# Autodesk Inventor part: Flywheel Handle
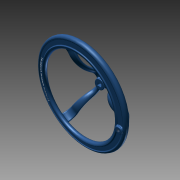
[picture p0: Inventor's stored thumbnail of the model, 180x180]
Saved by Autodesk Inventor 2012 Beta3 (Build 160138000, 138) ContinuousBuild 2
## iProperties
Created: 2010-12
Part Number: Flywheel Handle
Document SubType Name: Modeling
Designer: Thom Tremblay
Density: 1 g/cm^3
Material: Default
Author: Thom Tremblay
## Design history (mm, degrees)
sketch "Sketch2"
  geometry: L1 (0, 0)-(-11.43, 0); L2 (-11.43, 0)-(-11.43, 16.51); L3 (-11.43, 16.51)-(0, 16.51); L4 (0, 16.51)-(0, 0); L5 (-96.52, 66.04)-(-86.36, 66.04); L6 (-86.36, 76.2)-(-96.52, 76.2); L7 (-95.25, 74.93)-(-87.63, 74.93); L8 (-96.52, 76.2)-(-95.25, 74.93); L9 (-86.36, 76.2)-(-87.63, 74.93); A1 r 5.08 centre (-86.36, 71.12) between (-86.36, 66.04) and (-86.36, 76.2); A2 r 5.08 centre (-96.52, 71.12) between (-96.52, 76.2) and (-96.52, 66.04)
  constraints: 18 end point, 4 parallel, 4 point on circle, 4 tangent, 2 centre point, 2 horizontal, 2 perpendicular
  dimensions: "d6" = 16.51 distance of L1.end L2.end; "d7" = 22.86 diameter of L2 L4; "d10" = 5.08 radius of A1; "d11" = 20.32 dimension on A2 A1; "d12" = 3.81 distance from line of A1.centre L7; "d13" = 7.62 distance of L7.start L7.end; "d14" = 76.2 distance from line of L6.end L1; "d15" = 203.2 dimension on A2 L4
revolve "Revolution1" sketch "Sketch2" stored, may be unused: angle "d16" = 120 deg
sketch "Sketch3"
  geometry: L1 (-91.007, -8.89)-(-91.007, 8.89); A1 r 88.9 centre (0, 0) between (-88.479, 8.643) and (-88.479, -8.643); A2 r 93.98 centre (0, 0) between (-93.535, 9.137) and (-93.535, -9.137); A3 r 2.54 centre (-91.007, -8.89) between (-88.479, -8.643) and (-93.535, -9.137); A4 r 2.54 centre (-91.007, 8.89) between (-88.479, 8.643) and (-93.535, 9.137); 2 further points
  constraints: 8 point on circle, 4 centre point, 4 tangent, 2 end point, 1 coincident, 1 midpoint, 1 vertical
  dimensions: "d17" = 17.78 distance of L1.start L1.end; "d18" = 88.9 radius of A1; "d19" = 5.08 diameter of A4
workplane "Work Plane1"
sketch "Sketch4"
  geometry: C1 r 5.08 at (0, 0.635); 1 further point
  constraints: 1 centre point
  dimensions: "d20" = 10.16 diameter of C1; "d21" = 8.89 distance of C1.centre point (0, -8.255)
sketch "3D Sketch1"
sketch "Sketch5"
  geometry: L1 (-91.007, 66.04)-(-91.007, 79.034); L2 (-11.43, 8.89)-(3.26, 8.89); A1 r 19.955 centre (-11.43, 28.845) between (-29.248, 19.86) and (-11.43, 8.89); A2 r 45.954 centre (-70.28, -0.83) between (-29.248, 19.86) and (-70.149, 45.123); A3 r 20.917 centre (-70.09, 66.04) between (-91.007, 66.04) and (-70.149, 45.123); 1 further point
  constraints: 6 point on circle, 4 end point, 4 tangent, 3 centre point, 1 perpendicular, 1 vertical
loft "Loft1" sketch "3D Sketch1", "Sketch5" dims "d22" = 0, "d23" = 90 deg, "d24" = 0, "d25" = 90 deg, "d26" = 0, "d27" = 90 deg
fillet "Fillet1" dims "d28" = 2.54
pattern_circular "Circular Pattern1" dims "d30" = 360 deg
sketch "Sketch6"
  geometry: L1 (-5.08, 3.556)-(5.08, 3.556); L2 (5.08, 3.556)-(5.08, -3.556); L3 (5.08, -3.556)-(-5.08, -3.556); L4 (-5.08, -3.556)-(-5.08, 3.556); 3 further points
  constraints: 8 end point, 2 midpoint, 2 parallel, 1 horizontal, 1 horizontal alignment, 1 perpendicular, 1 vertical alignment
  dimensions: "d32" = 7.112 distance of L3.end L1.start; "d33" = 10.16 distance of L1.start L1.end
extrude "Extrusion2" cut sketch "Sketch6" stored distance "d34" = 25.4; taper "d35" = 0 deg
fillet "Fillet2" dims "d36" = 1.27
sketch "Sketch7"
  geometry: C1 r 6.35 at (91.44, 0); 1 further point
  constraints: 1 centre point
  dimensions: "d37" = 12.7 diameter of C1; "d38" = 91.44 distance of point (0, 0) C1.centre
extrude "Extrusion3" join sketch "Sketch7" distance "d39" = 3.81; taper "d40" = -2 deg
fillet "Fillet3" dims "d41" = 1.27
hole "Hole1" diameter "d44" = 4.9784; stored, may be unused: countersink angle "d48" = 82 deg, drill point angle "d50" = 118 deg; dims "d42" = 25.4, "d43" = 25.4, "d45" = 10.16, "d46" = 9.525, "d47" = 6.35, "d49" = 12.7
sketch "Sketch8"
  geometry: L1 (0, 0)-(-77.65, -44.831); L2 (0, 0)-(-89.662, 0); L3 (0, 0)-(-77.65, 44.831); A1 r 89.662 centre (0, 0) between (-77.65, 44.831) and (-76.203, -47.249); 1 further point
  constraints: 6 end point, 4 point on circle, 1 centre point, 1 coincident, 1 horizontal, 1 other
  dimensions: "d51" = 89.662 radius of A1; "d52" = 30 deg angle of L2 L3 (= 0.5 x d53); "d53" = 60 deg angle of L1 L3
emboss "Emboss1" sketch "Sketch8" dims "d56" = 0.762, "d57" = 0
fillet "Fillet4" dims "d58" = 1.27
body "Solid1"
node "3D Intersection1"
